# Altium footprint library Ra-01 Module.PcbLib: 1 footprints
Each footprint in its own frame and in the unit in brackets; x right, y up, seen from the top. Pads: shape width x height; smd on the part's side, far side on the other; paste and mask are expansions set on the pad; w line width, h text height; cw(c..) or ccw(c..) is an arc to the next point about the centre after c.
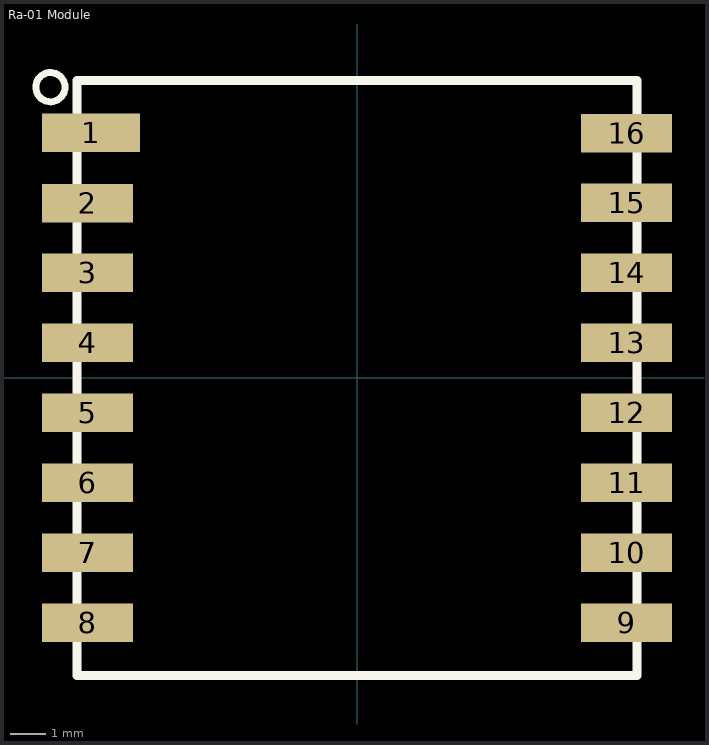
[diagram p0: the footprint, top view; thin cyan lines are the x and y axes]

## Ra-01 Module [mm]
pads (16):
  rect 2.8x1.1 smd: 1(-7.6,7.002)
  rect 2.6x1.1 smd: 2(-7.7,4.99) 3(-7.7,3.002) 4(-7.7,1.002) 5(-7.7,-0.998) 6(-7.7,-2.998) 7(-7.7,-4.998) 8(-7.7,-6.998) 9(7.7,-6.998) 10(7.7,-4.998) 11(7.7,-2.998) 12(7.7,-0.998) 13(7.7,1.002) 14(7.7,3.002) 15(7.7,5.002) 16(7.7,6.996)
Top Overlay:
  circle w0.2: c-8.763,8.306 r0.417
  lines w0.254: -8,-8.498 -8,8.502 8,8.502 8,-8.498 -8,-8.498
